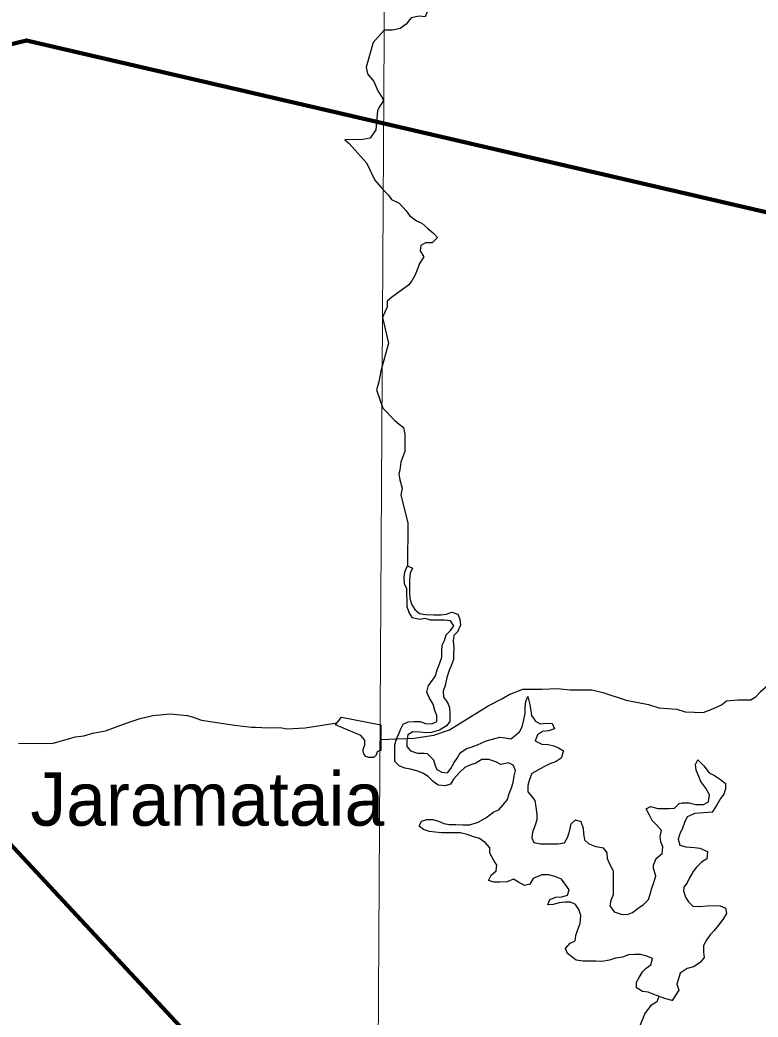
# Model space of a CAD drawing. Extents: x 553962 to 842807, y 8883888 to 9032388.
# Drawn here: x 716092 to 722992, y 8928988 to 8938306 of the extents above; entities that cross this region are included whole.
import ezdxf

# ---------------------------------------------------------------- set-up
doc = ezdxf.new("R2010")
doc.units = 0
doc.header["$LTSCALE"] = 200
for name, color, linetype, lineweight in [('1', 7, 'Continuous', 13), ('12', 7, 'Continuous', 25), ('21', 7, 'Continuous', 25), ('24', 7, 'Continuous', 25), ('9', 7, 'Continuous', 90)]:
    doc.layers.add(name, color=color, linetype=linetype, lineweight=lineweight)
doc.layers.add('41', color=7, linetype='Continuous')

msp = doc.modelspace()

# ---------------------------------------------------------------- linework, layer by layer
at = {"layer": '1'}
msp.add_lwpolyline([(719978.9, 9023574.5), (719561.6, 8949232.2), (719215.6, 8890710.6)], dxfattribs=at)
at = {"layer": '12'}
for points in [[(723524.2, 8932470.5), (723013.1, 8932023.2), (722964.6, 8931975.3), (722928.4, 8931953)], [(719465.7, 8931582), (719776.2, 8931594.6), (719960.1, 8931621.3), (720108, 8931671.9), (720470.6, 8931895.4), (720598.2, 8931961.4), (720664.5, 8932002), (720792.1, 8932052.7), (720970.4, 8932052.4), (721113, 8932057.2), (721235.3, 8932046.8), (721439, 8932046.4), (721540.8, 8932020.8), (721759.6, 8931949.1), (721968.3, 8931907.9), (722065, 8931877.2), (722233.1, 8931866.7), (722309.4, 8931841.1), (722477.5, 8931835.7), (722554, 8931861), (722651, 8931906.7), (722697, 8931942.3), (722804, 8931952.2), (722928.4, 8931953)], [(716324.2, 8931543.6), (716403.5, 8931548.6), (716611, 8931605.6), (716690.2, 8931616.7), (716773.7, 8931642.7), (716891.8, 8931664.4), (717093.4, 8931739.1), (717215.6, 8931777.9), (717335.2, 8931806.9), (717497.8, 8931823.2), (717656.3, 8931805.2), (717701.6, 8931794.1), (717788.3, 8931763.5), (718097.5, 8931715.5), (718256.9, 8931697.3), (718293.2, 8931696)], [(718293.2, 8931696), (718411.2, 8931691.7), (718463.6, 8931694.9), (718539.5, 8931689.8), (718584.8, 8931680.8), (718757, 8931689.8), (719057.1, 8931737.7)], [(716078.4, 8931547.1), (716324.2, 8931543.6)]]:
    msp.add_lwpolyline(points, dxfattribs=at)
at = {"layer": '21'}
msp.add_lwpolyline([(719466.9, 8931717.9), (719464.5, 8931480.1), (719451.4, 8931477.4), (719431, 8931467.2), (719420.8, 8931436.5), (719400.5, 8931413.5), (719380.2, 8931413.5), (719352.2, 8931413.5), (719324.2, 8931423.7), (719306.3, 8931446.7), (719301.3, 8931467.1), (719301.2, 8931487.6), (719306.3, 8931508), (719316.5, 8931531.1), (719316.5, 8931554.1), (719316.5, 8931577.1), (719296.1, 8931597.5), (719278.3, 8931620.5), (719041.6, 8931717.6), (719097.6, 8931791.8)], close=True, dxfattribs=at)
at = {"layer": '24'}
for points in [[(720060.8, 8938559.8), (720055.8, 8938559.8), (719994.6, 8938534.7), (719948.5, 8938494.2), (719922.7, 8938443.5), (719881.3, 8938336.8), (719825.4, 8938342.2), (719749, 8938327.4), (719702.8, 8938266.6), (719646.6, 8938226.2), (719575.3, 8938211.3), (719495.9, 8938211.8)], [(719495.9, 8938211.8), (719394.7, 8938096.4), (719328.4, 8937863.4), (719342.1, 8937802.6), (719401.1, 8937732.2), (719437, 8937644.3), (719483.8, 8937567.5), (719487.5, 8937545.9), (719449.3, 8937492.5), (719434.6, 8937455.6), (719420.2, 8937279.4), (719367.4, 8937201.3), (719297.2, 8937190.5), (719130.2, 8937185.6)], [(719130.2, 8937185.6), (719170.7, 8937152.3), (719333.3, 8936971.3), (719410.8, 8936807.6), (719495, 8936711.2)], [(719495, 8936711.2), (719536.3, 8936669.7), (719566.5, 8936628.7), (719637.5, 8936592.7), (719703.1, 8936520.9), (719733.3, 8936480), (719799.1, 8936428.7), (719849.8, 8936408), (719905.4, 8936356.8), (719961, 8936310.6), (719996.4, 8936274.7), (719945.2, 8936224.1), (719884.2, 8936224.5), (719838.2, 8936199.3), (719832.8, 8936148.4), (719868, 8936092.2), (719826.9, 8936031.3), (719806.1, 8935970.3), (719785.5, 8935924.6), (719754.6, 8935868.8), (719723.8, 8935828.3), (719667.5, 8935787.9), (719611.3, 8935747.5), (719565.3, 8935712.1), (719524.3, 8935676.7), (719524, 8935625.8), (719503.3, 8935575), (719482.6, 8935524.2), (719536.9, 8935284.5)], [(719536.9, 8935284.5), (719464.5, 8935025.4), (719447.8, 8934924.5), (719426.1, 8934849.8), (719483, 8934679.3)], [(719483, 8934679.3), (719595.3, 8934563.2), (719635.8, 8934527.3), (719676.2, 8934496.5), (719691.1, 8934435.3), (719690.7, 8934384.4), (719690.3, 8934323.2), (719690, 8934272.3), (719669.2, 8934217.6), (719651.2, 8934174.2), (719643, 8934099.5), (719634.9, 8934064), (719642.2, 8934009.8), (719665.6, 8933932.1), (719651.2, 8933868.8), (719718.1, 8933604.6), (719714.8, 8933203.5)], [(720541.5, 8931374.6), (720475.5, 8931395.4), (720409.4, 8931395.9), (720353.4, 8931360.9), (720298.5, 8931340.7), (720249.5, 8931320.4), (720203.3, 8931277.1), (720145.5, 8931210.6), (720116.7, 8931164.4), (720066.9, 8931148.5), (720000.8, 8931154), (719955.3, 8931189.9), (719909.8, 8931236.1), (719859.2, 8931266.9), (719803.4, 8931287.7), (719742.5, 8931303.4), (719691.7, 8931313.9), (719635.9, 8931334.6), (719595.5, 8931375.6), (719595.8, 8931426.6), (719596.2, 8931482.6), (719596.6, 8931533.5), (719612.2, 8931589.4), (719632.8, 8931635.2), (719653.5, 8931680.9), (719674.2, 8931726.6), (719720.1, 8931746.7), (719776.1, 8931751.4), (719832, 8931751), (719882.7, 8931730.3), (719943.8, 8931729.9), (719989.7, 8931750), (719990.1, 8931806.1), (719970, 8931852), (719955.2, 8931913.3), (719920, 8931969.5), (719894.9, 8932025.7), (719910.6, 8932086.7), (719941.4, 8932127.3), (719977.3, 8932178), (719993, 8932233.9), (720013.7, 8932289.8), (720034.5, 8932350.8), (720034.9, 8932411.9), (720040.3, 8932462.8), (720061, 8932508.6), (720076.6, 8932559.4), (720117.6, 8932599.9), (720148.4, 8932645.5), (720118.2, 8932691.6), (720062.3, 8932697), (719991.1, 8932697.5), (719930.1, 8932697.9), (719879.3, 8932713.5), (719828.4, 8932703.6), (719762.4, 8932719.3), (719732.2, 8932770.4), (719712.2, 8932821.5), (719712.6, 8932882.7), (719707.9, 8932938.7), (719708.3, 8932989.6), (719688.2, 8933035.6), (719683.6, 8933096.8), (719689, 8933147.7), (719714.8, 8933203.5), (719760.5, 8933182.9), (719739.8, 8933137.2), (719734.3, 8933071), (719733.8, 8933009.9), (719733.5, 8932953.8), (719738.2, 8932902.9), (719753.1, 8932846.7), (719783.2, 8932795.6), (719828.8, 8932759.7), (719884.6, 8932749.1), (719960.9, 8932748.6), (720027.1, 8932748.2), (720078, 8932753), (720129, 8932773), (720184.8, 8932752.3), (720204.8, 8932706.3), (720209.5, 8932650.2), (720183.6, 8932589.3), (720147.8, 8932553.8), (720142.3, 8932502.9), (720147, 8932436.7), (720146.6, 8932385.8), (720146.2, 8932329.7), (720125.6, 8932278.9), (720104.8, 8932228.1), (720084.1, 8932162), (720068.3, 8932085.7), (720047.6, 8932034.9), (720052.3, 8931978.8), (720087.5, 8931927.7), (720107.6, 8931881.7), (720112.2, 8931820.6), (720111.7, 8931749.2), (720080.9, 8931708.7), (720014.5, 8931668.4), (719938.1, 8931648.5)], [(719938.1, 8931648.5), (719882.1, 8931643.8), (719831.3, 8931649.2), (719765.2, 8931654.7), (719719.2, 8931624.4), (719708.7, 8931568.5), (719708.3, 8931517.5), (719743.7, 8931476.5), (719809.6, 8931455.7), (719870.7, 8931455.3), (719899.8, 8931451.2), (719959.3, 8931391.6), (719974.2, 8931339.4), (719989.1, 8931302.2), (720037.3, 8931276), (720088.1, 8931270.6), (720118.9, 8931311.1), (720149.8, 8931367), (720180.6, 8931407.5), (720206.4, 8931458.3), (720267.7, 8931498.7), (720309.2, 8931510.9), (720368.7, 8931533.2), (720450.6, 8931570.5), (720578.7, 8931603.6), (720629.5, 8931598.2), (720680.3, 8931587.7), (720721.2, 8931618), (720762.1, 8931653.4), (720787.8, 8931699.1), (720803.6, 8931765.2), (720814.2, 8931826.2), (720814.5, 8931882.3), (720820, 8931938.3), (720840.7, 8931984), (720855.5, 8931922.8), (720865.3, 8931871.8), (720875.1, 8931805.5), (720910.3, 8931754.3), (720955.9, 8931728.6), (721017, 8931733.3), (721067.8, 8931732.9), (721087.8, 8931681.9), (721031.7, 8931661.8), (720975.8, 8931657.1), (720929.8, 8931626.8), (720909, 8931570.9), (720969.9, 8931540), (721030.9, 8931534.5), (721081.7, 8931524), (721127.3, 8931503.3), (721172.9, 8931477.6), (721152, 8931406.4), (721106.1, 8931376.1), (721044.9, 8931356.1), (720988.7, 8931325.9), (720932.6, 8931295.7), (720876.4, 8931265.5), (720855.7, 8931209.6), (720840.1, 8931153.7), (720839.6, 8931092.6), (720875, 8931051.6), (720905.2, 8931010.6), (720914.9, 8930949.5), (720924.7, 8930883.2), (720924.3, 8930832.2), (720908.7, 8930781.4), (720882.8, 8930715.3), (720877.4, 8930664.4), (720897.4, 8930618.5), (720958.4, 8930607.9), (721019.4, 8930607.5), (721070.3, 8930607.2), (721121.1, 8930606.8), (721182.2, 8930616.6), (721213.1, 8930672.5), (721233.9, 8930733.5), (721244.5, 8930794.5), (721285.4, 8930829.9), (721336.2, 8930814.3), (721356.1, 8930753.1), (721360.8, 8930702.1), (721370.6, 8930646), (721406, 8930610.1), (721461.7, 8930584.3), (721543, 8930568.5), (721578.3, 8930522.4), (721583, 8930471.4), (721603, 8930420.4), (721638.2, 8930353.9), (721637.8, 8930292.8), (721637.4, 8930241.9), (721637.1, 8930190.9), (721636.6, 8930129.8), (721615.9, 8930079), (721605.4, 8930028.1), (721645.7, 8929971.8), (721711.7, 8929951), (721772.7, 8929945.6), (721818.6, 8929965.6), (721869.7, 8930006.1)], [(722189.3, 8929143.2), (722128.4, 8929158.8), (722042.1, 8929189.9), (721966.1, 8929221), (721910.2, 8929226.4), (721854.5, 8929262.5), (721854.8, 8929313.4), (721880.6, 8929359.1), (721911.4, 8929409.8), (721947.3, 8929445.2), (721988.2, 8929475.5), (722003.8, 8929536.6), (721953.1, 8929557.3), (721892.2, 8929572.9), (721836.2, 8929573.3), (721780.3, 8929568.6), (721724.2, 8929548.6), (721658, 8929538.8), (721601.9, 8929518.8), (721530.6, 8929509), (721474.7, 8929509.4), (721418.7, 8929509.8), (721357.7, 8929510.2), (721291.7, 8929520.8), (721251.2, 8929551.6), (721210.7, 8929582.4), (721190.7, 8929628.4), (721236.8, 8929679), (721282.7, 8929699.1), (721288.2, 8929750), (721309, 8929816.1), (721329.6, 8929861.8), (721335.2, 8929938.2), (721315.3, 8929994.3), (721285.1, 8930040.4), (721239.4, 8930061), (721188.6, 8930061.4), (721132.6, 8930056.6), (721076.5, 8930041.7), (721025.6, 8930036.9), (721046.3, 8930087.8), (721102.4, 8930107.8), (721158.4, 8930112.5), (721209.4, 8930127.5), (721225, 8930178.3), (721189.7, 8930229.5), (721154.4, 8930275.5), (721093.6, 8930301.4), (721037.7, 8930317), (720971.6, 8930317.4), (720890, 8930282.3), (720859.1, 8930231.6), (720808.2, 8930216.6), (720752.4, 8930247.6), (720706.9, 8930278.4), (720645.7, 8930253.3), (720579.5, 8930248.7), (720523.6, 8930249), (720472.8, 8930264.6), (720498.6, 8930315.4), (720544.7, 8930355.8), (720550.1, 8930406.8), (720519.9, 8930457.9), (720484.7, 8930519.2), (720485.1, 8930570.2), (720444.7, 8930616.3), (720389.1, 8930657.4), (720333.2, 8930673), (720272.3, 8930693.8), (720211.4, 8930709.5), (720160.5, 8930709.8), (720094.4, 8930710.2), (720033.4, 8930710.6), (719972.4, 8930716.1), (719921.6, 8930721.5), (719865.8, 8930742.2), (719825.3, 8930773.1), (719845.9, 8930818.8), (719896.9, 8930833.7), (719952.8, 8930833.4), (720003.6, 8930817.8), (720054.3, 8930797.1), (720105.1, 8930786.6), (720166.2, 8930786.2), (720232.3, 8930785.7), (720298.4, 8930785.3), (720374.8, 8930810.3), (720446.3, 8930850.6), (720523, 8930906.1), (720568.9, 8930926.2), (720609.9, 8930971.8), (720651, 8931022.5), (720666.6, 8931078.4), (720687.3, 8931129.2), (720702.9, 8931180), (720713.5, 8931241.1), (720724, 8931292), (720704, 8931343), (720658.4, 8931363.7), (720587.1, 8931348.9), (720541.5, 8931374.6)], [(721869.7, 8930006.1), (721920.8, 8930041.4), (721966.9, 8930086.9), (721982.5, 8930137.8), (721998.2, 8930193.7), (722018.9, 8930244.5), (722035.3, 8930306.7), (722014.7, 8930377), (722015.4, 8930406.4), (722040.8, 8930468.5), (722095, 8930516.1), (722102.6, 8930580.2), (722082.5, 8930626.2), (722077.8, 8930677.1), (722088.4, 8930733.1), (722042.9, 8930784.3), (722002.5, 8930825.3), (721977.5, 8930876.4), (721947.3, 8930932.7), (721985.5, 8930954.9), (722054.2, 8930937.1), (722105, 8930936.7), (722161, 8930936.4), (722211.9, 8930941.1), (722254.4, 8930984.8), (722283.4, 8930991.6), (722349.5, 8930991.2), (722410.5, 8930975.5), (722481.7, 8930975.1), (722527.6, 8931000.2), (722538.2, 8931066.4), (722503.1, 8931127.7), (722457.7, 8931189.2), (722437.7, 8931235.1), (722412.7, 8931296.4), (722407.9, 8931347.4), (722428.6, 8931393.1), (722484.1, 8931336.7), (722534.6, 8931270.2), (722585.2, 8931244.4), (722640.9, 8931208.4), (722686.5, 8931172.4), (722686.1, 8931121.5), (722670.5, 8931070.6), (722639.7, 8931030.1), (722603.7, 8930964.1), (722562.5, 8930903.2), (722483.5, 8930896.6), (722400.2, 8930890.6), (722328.7, 8930860.8), (722304.9, 8930807.2), (722286.8, 8930752.2), (722261.1, 8930701.4), (722245.5, 8930650.6), (722260.3, 8930594.4), (722316.2, 8930578.8), (722397.5, 8930573.2), (722448.3, 8930567.8), (722519.3, 8930536.8), (722513.8, 8930465.5), (722462.7, 8930435.2), (722416.6, 8930389.7), (722385.8, 8930349.1), (722349.8, 8930288.2), (722329.1, 8930242.5), (722298.3, 8930202), (722294.2, 8930167.1), (722313, 8930110.2), (722343.2, 8930064.2), (722383.6, 8930023.1), (722444.6, 8930022.8), (722515.8, 8930027.4), (722587.1, 8930032), (722637.9, 8930026.6), (722688.6, 8930005.9), (722698.4, 8929954.9), (722662.5, 8929899.1), (722621.4, 8929848.4), (722580.4, 8929797.8), (722544.5, 8929757.2), (722513.7, 8929711.6), (722482.8, 8929655.8), (722482.3, 8929594.6), (722487.1, 8929543.7), (722451.2, 8929498), (722389.8, 8929457.7), (722328.7, 8929442.8), (722262.3, 8929397.4), (722246.7, 8929346.5), (722231.1, 8929295.7), (722251, 8929239.5), (722189.3, 8929143.2)], [(722065, 8929181.7), (722047.1, 8929132.1), (721985.8, 8929091.8), (721934.5, 8929020.8), (721908.6, 8928959.8), (721882.8, 8928898.9), (721862, 8928837.9), (721836.2, 8928792.2), (721826.6, 8928771.5)]]:
    msp.add_lwpolyline(points, dxfattribs=at)
at = {"layer": '24', "lineweight": 13}
for points in [[(720541.5, 8931374.6), (720475.5, 8931395.4), (720409.4, 8931395.9), (720353.4, 8931360.9), (720298.5, 8931340.7), (720249.5, 8931320.4), (720203.3, 8931277.1), (720145.5, 8931210.6), (720116.7, 8931164.4), (720066.9, 8931148.5), (720000.8, 8931154), (719955.3, 8931189.9), (719909.8, 8931236.1), (719859.2, 8931266.9), (719803.4, 8931287.7), (719742.5, 8931303.4), (719691.7, 8931313.9), (719635.9, 8931334.6), (719595.5, 8931375.6), (719595.8, 8931426.6), (719596.2, 8931482.6), (719596.6, 8931533.5), (719612.2, 8931589.4), (719632.8, 8931635.2), (719653.5, 8931680.9), (719674.2, 8931726.6), (719720.1, 8931746.7), (719776.1, 8931751.4), (719832, 8931751), (719882.7, 8931730.3), (719943.8, 8931729.9), (719989.7, 8931750), (719990.1, 8931806.1), (719970, 8931852), (719955.2, 8931913.3), (719920, 8931969.5), (719894.9, 8932025.7), (719910.6, 8932086.7), (719941.4, 8932127.3), (719977.3, 8932178), (719993, 8932233.9), (720013.7, 8932289.8), (720034.5, 8932350.8), (720034.9, 8932411.9), (720040.3, 8932462.8), (720061, 8932508.6), (720076.6, 8932559.4), (720117.6, 8932599.9), (720148.4, 8932645.5), (720118.2, 8932691.6), (720062.3, 8932697), (719991.1, 8932697.5), (719930.1, 8932697.9), (719879.3, 8932713.5), (719828.4, 8932703.6), (719762.4, 8932719.3), (719732.2, 8932770.4), (719712.2, 8932821.5), (719712.6, 8932882.7), (719707.9, 8932938.7), (719708.3, 8932989.6), (719688.2, 8933035.6), (719683.6, 8933096.8), (719689, 8933147.7), (719714.8, 8933203.5), (719760.5, 8933182.9), (719739.8, 8933137.2), (719734.3, 8933071), (719733.8, 8933009.9), (719733.5, 8932953.8), (719738.2, 8932902.9), (719753.1, 8932846.7), (719783.2, 8932795.6), (719828.8, 8932759.7), (719884.6, 8932749.1), (719960.9, 8932748.6), (720027.1, 8932748.2), (720078, 8932753), (720129, 8932773), (720184.8, 8932752.3), (720204.8, 8932706.3), (720209.5, 8932650.2), (720183.6, 8932589.3), (720147.8, 8932553.8), (720142.3, 8932502.9), (720147, 8932436.7), (720146.6, 8932385.8), (720146.2, 8932329.7), (720125.6, 8932278.9), (720104.8, 8932228.1), (720084.1, 8932162), (720068.3, 8932085.7), (720047.6, 8932034.9), (720052.3, 8931978.8), (720087.5, 8931927.7), (720107.6, 8931881.7), (720112.2, 8931820.6), (720111.7, 8931749.2), (720080.9, 8931708.7), (720014.5, 8931668.4), (719938.1, 8931648.5)], [(719938.1, 8931648.5), (719882.1, 8931643.8), (719831.3, 8931649.2), (719765.2, 8931654.7), (719719.2, 8931624.4), (719708.7, 8931568.5), (719708.3, 8931517.5), (719743.7, 8931476.5), (719809.6, 8931455.7), (719870.7, 8931455.3), (719899.8, 8931451.2), (719959.3, 8931391.6), (719974.2, 8931339.4), (719989.1, 8931302.2), (720037.3, 8931276), (720088.1, 8931270.6), (720118.9, 8931311.1), (720149.8, 8931367), (720180.6, 8931407.5), (720206.4, 8931458.3), (720267.7, 8931498.7), (720309.2, 8931510.9), (720368.7, 8931533.2), (720450.6, 8931570.5), (720578.7, 8931603.6), (720629.5, 8931598.2), (720680.3, 8931587.7), (720721.2, 8931618), (720762.1, 8931653.4), (720787.8, 8931699.1), (720803.6, 8931765.2), (720814.2, 8931826.2), (720814.5, 8931882.3), (720820, 8931938.3), (720840.7, 8931984), (720855.5, 8931922.8), (720865.3, 8931871.8), (720875.1, 8931805.5), (720910.3, 8931754.3), (720955.9, 8931728.6), (721017, 8931733.3), (721067.8, 8931732.9), (721087.8, 8931681.9), (721031.7, 8931661.8), (720975.8, 8931657.1), (720929.8, 8931626.8), (720909, 8931570.9), (720969.9, 8931540), (721030.9, 8931534.5), (721081.7, 8931524), (721127.3, 8931503.3), (721172.9, 8931477.6), (721152, 8931406.4), (721106.1, 8931376.1), (721044.9, 8931356.1), (720988.7, 8931325.9), (720932.6, 8931295.7), (720876.4, 8931265.5), (720855.7, 8931209.6), (720840.1, 8931153.7), (720839.6, 8931092.6), (720875, 8931051.6), (720905.2, 8931010.6), (720914.9, 8930949.5), (720924.7, 8930883.2), (720924.3, 8930832.2), (720908.7, 8930781.4), (720882.8, 8930715.3), (720877.4, 8930664.4), (720897.4, 8930618.5), (720958.4, 8930607.9), (721019.4, 8930607.5), (721070.3, 8930607.2), (721121.1, 8930606.8), (721182.2, 8930616.6), (721213.1, 8930672.5), (721233.9, 8930733.5), (721244.5, 8930794.5), (721285.4, 8930829.9), (721336.2, 8930814.3), (721356.1, 8930753.1), (721360.8, 8930702.1), (721370.6, 8930646), (721406, 8930610.1), (721461.7, 8930584.3), (721543, 8930568.5), (721578.3, 8930522.4), (721583, 8930471.4), (721603, 8930420.4), (721638.2, 8930353.9), (721637.8, 8930292.8), (721637.4, 8930241.9), (721637.1, 8930190.9), (721636.6, 8930129.8), (721615.9, 8930079), (721605.4, 8930028.1), (721645.7, 8929971.8), (721711.7, 8929951), (721772.7, 8929945.6), (721818.6, 8929965.6), (721869.7, 8930006.1)], [(722189.3, 8929143.2), (722128.4, 8929158.8), (722042.1, 8929189.9), (721966.1, 8929221), (721910.2, 8929226.4), (721854.5, 8929262.5), (721854.8, 8929313.4), (721880.6, 8929359.1), (721911.4, 8929409.8), (721947.3, 8929445.2), (721988.2, 8929475.5), (722003.8, 8929536.6), (721953.1, 8929557.3), (721892.2, 8929572.9), (721836.2, 8929573.3), (721780.3, 8929568.6), (721724.2, 8929548.6), (721658, 8929538.8), (721601.9, 8929518.8), (721530.6, 8929509), (721474.7, 8929509.4), (721418.7, 8929509.8), (721357.7, 8929510.2), (721291.7, 8929520.8), (721251.2, 8929551.6), (721210.7, 8929582.4), (721190.7, 8929628.4), (721236.8, 8929679), (721282.7, 8929699.1), (721288.2, 8929750), (721309, 8929816.1), (721329.6, 8929861.8), (721335.2, 8929938.2), (721315.3, 8929994.3), (721285.1, 8930040.4), (721239.4, 8930061), (721188.6, 8930061.4), (721132.6, 8930056.6), (721076.5, 8930041.7), (721025.6, 8930036.9), (721046.3, 8930087.8), (721102.4, 8930107.8), (721158.4, 8930112.5), (721209.4, 8930127.5), (721225, 8930178.3), (721189.7, 8930229.5), (721154.4, 8930275.5), (721093.6, 8930301.4), (721037.7, 8930317), (720971.6, 8930317.4), (720890, 8930282.3), (720859.1, 8930231.6), (720808.2, 8930216.6), (720752.4, 8930247.6), (720706.9, 8930278.4), (720645.7, 8930253.3), (720579.5, 8930248.7), (720523.6, 8930249), (720472.8, 8930264.6), (720498.6, 8930315.4), (720544.7, 8930355.8), (720550.1, 8930406.8), (720519.9, 8930457.9), (720484.7, 8930519.2), (720485.1, 8930570.2), (720444.7, 8930616.3), (720389.1, 8930657.4), (720333.2, 8930673), (720272.3, 8930693.8), (720211.4, 8930709.5), (720160.5, 8930709.8), (720094.4, 8930710.2), (720033.4, 8930710.6), (719972.4, 8930716.1), (719921.6, 8930721.5), (719865.8, 8930742.2), (719825.3, 8930773.1), (719845.9, 8930818.8), (719896.9, 8930833.7), (719952.8, 8930833.4), (720003.6, 8930817.8), (720054.3, 8930797.1), (720105.1, 8930786.6), (720166.2, 8930786.2), (720232.3, 8930785.7), (720298.4, 8930785.3), (720374.8, 8930810.3), (720446.3, 8930850.6), (720523, 8930906.1), (720568.9, 8930926.2), (720609.9, 8930971.8), (720651, 8931022.5), (720666.6, 8931078.4), (720687.3, 8931129.2), (720702.9, 8931180), (720713.5, 8931241.1), (720724, 8931292), (720704, 8931343), (720658.4, 8931363.7), (720587.1, 8931348.9), (720541.5, 8931374.6)], [(721869.7, 8930006.1), (721920.8, 8930041.4), (721966.9, 8930086.9), (721982.5, 8930137.8), (721998.2, 8930193.7), (722018.9, 8930244.5), (722035.3, 8930306.7), (722014.7, 8930377), (722015.4, 8930406.4), (722040.8, 8930468.5), (722095, 8930516.1), (722102.6, 8930580.2), (722082.5, 8930626.2), (722077.8, 8930677.1), (722088.4, 8930733.1), (722042.9, 8930784.3), (722002.5, 8930825.3), (721977.5, 8930876.4), (721947.3, 8930932.7), (721985.5, 8930954.9), (722054.2, 8930937.1), (722105, 8930936.7), (722161, 8930936.4), (722211.9, 8930941.1), (722254.4, 8930984.8), (722283.4, 8930991.6), (722349.5, 8930991.2), (722410.5, 8930975.5), (722481.7, 8930975.1), (722527.6, 8931000.2), (722538.2, 8931066.4), (722503.1, 8931127.7), (722457.7, 8931189.2), (722437.7, 8931235.1), (722412.7, 8931296.4), (722407.9, 8931347.4), (722428.6, 8931393.1), (722484.1, 8931336.7), (722534.6, 8931270.2), (722585.2, 8931244.4), (722640.9, 8931208.4), (722686.5, 8931172.4), (722686.1, 8931121.5), (722670.5, 8931070.6), (722639.7, 8931030.1), (722603.7, 8930964.1), (722562.5, 8930903.2), (722483.5, 8930896.6), (722400.2, 8930890.6), (722328.7, 8930860.8), (722304.9, 8930807.2), (722286.8, 8930752.2), (722261.1, 8930701.4), (722245.5, 8930650.6), (722260.3, 8930594.4), (722316.2, 8930578.8), (722397.5, 8930573.2), (722448.3, 8930567.8), (722519.3, 8930536.8), (722513.8, 8930465.5), (722462.7, 8930435.2), (722416.6, 8930389.7), (722385.8, 8930349.1), (722349.8, 8930288.2), (722329.1, 8930242.5), (722298.3, 8930202), (722294.2, 8930167.1), (722313, 8930110.2), (722343.2, 8930064.2), (722383.6, 8930023.1), (722444.6, 8930022.8), (722515.8, 8930027.4), (722587.1, 8930032), (722637.9, 8930026.6), (722688.6, 8930005.9), (722698.4, 8929954.9), (722662.5, 8929899.1), (722621.4, 8929848.4), (722580.4, 8929797.8), (722544.5, 8929757.2), (722513.7, 8929711.6), (722482.8, 8929655.8), (722482.3, 8929594.6), (722487.1, 8929543.7), (722451.2, 8929498), (722389.8, 8929457.7), (722328.7, 8929442.8), (722262.3, 8929397.4), (722246.7, 8929346.5), (722231.1, 8929295.7), (722251, 8929239.5), (722189.3, 8929143.2)]]:
    msp.add_lwpolyline(points, dxfattribs=at)
at = {"layer": '9'}
msp.add_line((710319.1, 8936704.6), (720989.4, 8925252.2), dxfattribs=at)
msp.add_lwpolyline([(696242, 8937672.8), (702061.8, 8937200.5), (702208.9, 8933124.7), (710319.1, 8936704.6), (716154, 8938115.2), (724825.2, 8936103.1), (730092.7, 8935013.9)], dxfattribs=at)

# ---------------------------------------------------------------- texts
at = {"layer": '41'}
msp.add_text('Jaramataia', height=500, dxfattribs=at).set_placement((716190.3, 8930776.7))

doc.saveas('drawing.dxf')
